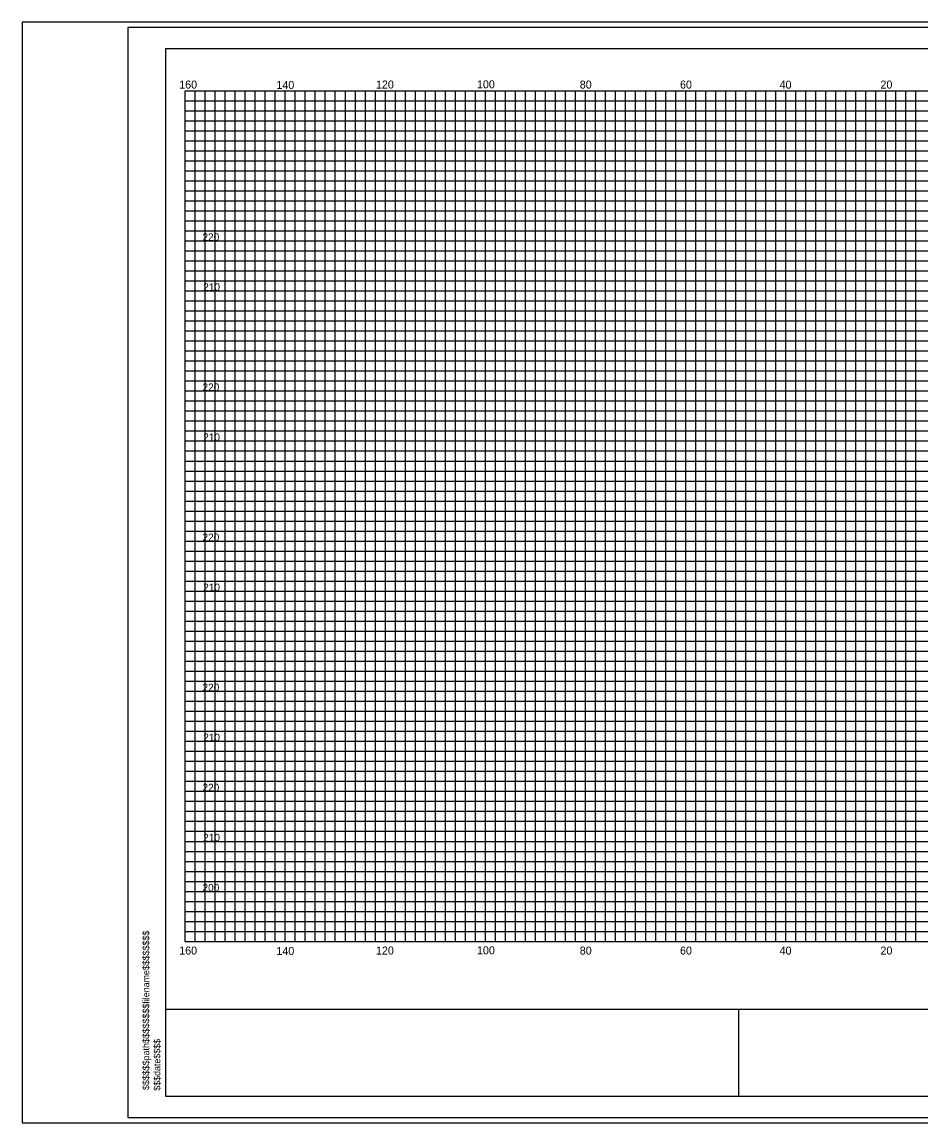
# Model space of a CAD drawing. Extents: x 967 to 1326, y 964 to 2584.
# Drawn here: x 967.4 to 1147, y 963.7 to 1183.7 of the extents above; entities that cross this region are included whole.
import ezdxf

# ---------------------------------------------------------------- set-up
doc = ezdxf.new("R2010")
doc.units = 0
for name, color, linetype in [('Default', 7, 'Continuous'), ('RD_GPK_XS_Cell', 7, 'Continuous'), ('RD_XS_ExGround', 7, 'Continuous'), ('RD_XS_ExPaveRet', 7, 'Continuous'), ('RD_XS_Misc_Line', 7, 'Continuous'), ('RD_XS_TX_Elev_EX', 7, 'Continuous')]:
    doc.layers.add(name, color=color, linetype=linetype)

msp = doc.modelspace()

# ---------------------------------------------------------------- linework, layer by layer
at = {"layer": 'RD_GPK_XS_Cell'}
for p, q in [((1000, 1170), (1320, 1170)), ((1000, 1000), (1000, 1170)), ((1010, 1000), (1010, 1170)), ((1020, 1000), (1020, 1170)), ((1030, 1000), (1030, 1170)), ((1040, 1000), (1040, 1170)), ((1050, 1000), (1050, 1170)), ((1060, 1000), (1060, 1170)), ((1070, 1000), (1070, 1170)), ((1080, 1000), (1080, 1170)), ((1090, 1000), (1090, 1170)), ((1100, 1000), (1100, 1170)), ((1110, 1000), (1110, 1170)), ((1120, 1000), (1120, 1170)), ((1130, 1000), (1130, 1170)), ((1140, 1000), (1140, 1170)), ((1000, 1160), (1320, 1160)), ((1000, 1150), (1320, 1150)), ((1000, 1140), (1320, 1140)), ((1000, 1130), (1320, 1130)), ((1000, 1120), (1320, 1120)), ((1000, 1110), (1320, 1110)), ((1000, 1100), (1320, 1100)), ((1000, 1090), (1320, 1090)), ((1000, 1080), (1320, 1080)), ((1000, 1070), (1320, 1070)), ((1000, 1060), (1320, 1060)), ((1000, 1050), (1320, 1050)), ((1000, 1040), (1320, 1040)), ((1000, 1030), (1320, 1030)), ((1000, 1020), (1320, 1020)), ((1000, 1010), (1320, 1010)), ((1000, 1000), (1320, 1000))]:
    msp.add_line(p, q, dxfattribs=at)
at = {"layer": 'RD_XS_ExGround'}
for p, q in [((1002, 1000), (1002, 1170)), ((1004, 1000), (1004, 1170)), ((1006, 1000), (1006, 1170)), ((1008, 1000), (1008, 1170)), ((1012, 1000), (1012, 1170)), ((1014, 1000), (1014, 1170)), ((1016, 1000), (1016, 1170)), ((1018, 1000), (1018, 1170)), ((1022, 1000), (1022, 1170)), ((1024, 1000), (1024, 1170)), ((1026, 1000), (1026, 1170)), ((1028, 1000), (1028, 1170)), ((1032, 1000), (1032, 1170)), ((1034, 1000), (1034, 1170)), ((1036, 1000), (1036, 1170)), ((1038, 1000), (1038, 1170)), ((1042, 1000), (1042, 1170)), ((1044, 1000), (1044, 1170)), ((1046, 1000), (1046, 1170)), ((1048, 1000), (1048, 1170)), ((1052, 1000), (1052, 1170)), ((1054, 1000), (1054, 1170)), ((1056, 1000), (1056, 1170)), ((1058, 1000), (1058, 1170)), ((1062, 1000), (1062, 1170)), ((1064, 1000), (1064, 1170)), ((1066, 1000), (1066, 1170)), ((1068, 1000), (1068, 1170)), ((1072, 1000), (1072, 1170)), ((1074, 1000), (1074, 1170)), ((1076, 1000), (1076, 1170)), ((1078, 1000), (1078, 1170)), ((1082, 1000), (1082, 1170)), ((1084, 1000), (1084, 1170)), ((1086, 1000), (1086, 1170)), ((1088, 1000), (1088, 1170)), ((1092, 1000), (1092, 1170)), ((1094, 1000), (1094, 1170)), ((1096, 1000), (1096, 1170)), ((1098, 1000), (1098, 1170)), ((1102, 1000), (1102, 1170)), ((1104, 1000), (1104, 1170)), ((1106, 1000), (1106, 1170)), ((1108, 1000), (1108, 1170)), ((1112, 1000), (1112, 1170)), ((1114, 1000), (1114, 1170)), ((1116, 1000), (1116, 1170)), ((1118, 1000), (1118, 1170)), ((1122, 1000), (1122, 1170)), ((1124, 1000), (1124, 1170)), ((1126, 1000), (1126, 1170)), ((1128, 1000), (1128, 1170)), ((1132, 1000), (1132, 1170)), ((1134, 1000), (1134, 1170)), ((1136, 1000), (1136, 1170)), ((1138, 1000), (1138, 1170)), ((1142, 1000), (1142, 1170)), ((1144, 1000), (1144, 1170)), ((1146, 1000), (1146, 1170)), ((1000, 1168), (1320, 1168)), ((1000, 1166), (1320, 1166)), ((1000, 1164), (1320, 1164)), ((1000, 1162), (1320, 1162)), ((1000, 1158), (1320, 1158)), ((1000, 1156), (1320, 1156)), ((1000, 1154), (1320, 1154)), ((1000, 1152), (1320, 1152)), ((1000, 1148), (1320, 1148)), ((1000, 1146), (1320, 1146)), ((1000, 1144), (1320, 1144)), ((1000, 1142), (1320, 1142)), ((1000, 1138), (1320, 1138)), ((1000, 1136), (1320, 1136)), ((1000, 1134), (1320, 1134)), ((1000, 1132), (1320, 1132)), ((1000, 1128), (1320, 1128)), ((1000, 1126), (1320, 1126)), ((1000, 1124), (1320, 1124)), ((1000, 1122), (1320, 1122)), ((1000, 1118), (1320, 1118)), ((1000, 1116), (1320, 1116)), ((1000, 1114), (1320, 1114)), ((1000, 1112), (1320, 1112)), ((1000, 1108), (1320, 1108)), ((1000, 1106), (1320, 1106)), ((1000, 1104), (1320, 1104)), ((1000, 1102), (1320, 1102)), ((1000, 1098), (1320, 1098)), ((1000, 1096), (1320, 1096)), ((1000, 1094), (1320, 1094)), ((1000, 1092), (1320, 1092)), ((1000, 1088), (1320, 1088)), ((1000, 1086), (1320, 1086)), ((1000, 1084), (1320, 1084)), ((1000, 1082), (1320, 1082)), ((1000, 1078), (1320, 1078)), ((1000, 1076), (1320, 1076)), ((1000, 1074), (1320, 1074)), ((1000, 1072), (1320, 1072)), ((1000, 1068), (1320, 1068)), ((1000, 1066), (1320, 1066)), ((1000, 1064), (1320, 1064)), ((1000, 1062), (1320, 1062)), ((1000, 1058), (1320, 1058)), ((1000, 1056), (1320, 1056)), ((1000, 1054), (1320, 1054)), ((1000, 1052), (1320, 1052)), ((1000, 1048), (1320, 1048)), ((1000, 1046), (1320, 1046)), ((1000, 1044), (1320, 1044)), ((1000, 1042), (1320, 1042)), ((1000, 1038), (1320, 1038)), ((1000, 1036), (1320, 1036)), ((1000, 1034), (1320, 1034)), ((1000, 1032), (1320, 1032)), ((1000, 1028), (1320, 1028)), ((1000, 1026), (1320, 1026)), ((1000, 1024), (1320, 1024)), ((1000, 1022), (1320, 1022)), ((1000, 1018), (1320, 1018)), ((1000, 1016), (1320, 1016)), ((1000, 1014), (1320, 1014)), ((1000, 1012), (1320, 1012)), ((1000, 1008), (1320, 1008)), ((1000, 1006), (1320, 1006)), ((1000, 1004), (1320, 1004)), ((1000, 1002), (1320, 1002))]:
    msp.add_line(p, q, dxfattribs=at)
at = {"layer": 'RD_XS_ExPaveRet'}
for points in [[(967.41, 963.72), (1326.28, 963.72), (1326.28, 1183.72), (967.41, 1183.72)], [(988.52, 964.84), (1326.28, 964.84), (1326.28, 1182.6), (988.52, 1182.6)]]:
    msp.add_lwpolyline(points, close=True, dxfattribs=at)
at = {"layer": 'RD_XS_TX_Elev_EX'}
for p, q in [((996.11, 968.98), (996.11, 1178.46)), ((996.11, 1178.46), (1323.89, 1178.46)), ((996.11, 986.49), (1323.89, 986.49)), ((1110.59, 968.98), (1110.59, 986.56)), ((1323.89, 968.98), (996.11, 968.98))]:
    msp.add_line(p, q, dxfattribs=at)

# ---------------------------------------------------------------- texts
at = {"layer": 'Default'}
for s, p in [('220', (1003.47, 1140)), ('210', (1003.61, 1130)), ('220', (1003.47, 1110)), ('210', (1003.61, 1100)), ('220', (1003.47, 1080)), ('210', (1003.61, 1070)), ('220', (1003.47, 1050)), ('210', (1003.61, 1040)), ('220', (1003.47, 1030)), ('210', (1003.61, 1020)), ('200', (1003.47, 1010))]:
    msp.add_text(s, height=1.5, dxfattribs=at).set_placement(p)
for s, p in [('$$$$$$path$$$$$$$$filename$$$$$$$$', (992.83, 970.31)), ('$$$date$$$$', (995.04, 970.17))]:
    msp.add_text(s, height=1.3258, rotation=90, dxfattribs=at).set_placement(p)
at = {"layer": 'RD_XS_Misc_Line'}
for s, p in [('160', (998.81, 1170.42)), ('140', (1018.23, 1170.34)), ('120', (1038.12, 1170.43)), ('100', (1058.3, 1170.47)), ('80', (1078.84, 1170.42)), ('60', (1098.86, 1170.42)), ('40', (1118.75, 1170.41)), ('20', (1138.91, 1170.42)), ('160', (998.81, 997.37)), ('140', (1018.23, 997.29)), ('120', (1038.12, 997.38)), ('100', (1058.3, 997.42)), ('80', (1078.84, 997.37)), ('60', (1098.86, 997.37)), ('40', (1118.75, 997.36)), ('20', (1138.91, 997.37))]:
    msp.add_text(s, height=1.6, dxfattribs=at).set_placement(p)

doc.saveas('drawing.dxf')
